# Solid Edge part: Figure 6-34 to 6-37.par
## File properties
Author: Ashutosh-CADCIM
Template: Iso Metric Part.par
Last saved by: CADCIM_Sonam
Revision: 2
Application: Solid Edge
Accuracy: 0.990
Username: Ashutosh-CADCIM
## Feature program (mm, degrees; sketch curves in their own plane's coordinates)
base feature "unnamed BaseFeature 1"
sketch for "unnamed Protrusion 1" plane through (0, 0, 0) normal (0, -1, 0) x-axis (1, 0, 0)
  line (0, 100) -> (0, 0)
  line (0, 0) -> (100, 0)
  line (100, 0) -> (100, 20)
  line (100, 20) -> (20, 20)
  line (20, 20) -> (20, 100)
  line (20, 100) -> (0, 100)
  dimension (linear) = 100
extrude "unnamed Protrusion 1" add finite 100 symmetric
sketch for "ExtrudedCutout_1" plane through (60, 0, 20) normal (0, 0, 1) x-axis (0, 1, 0)
  line (10, -20) -> (-10, -20)
  line (-10, -20) -> (-10, 20)
  line (-10, 20) -> (10, 20)
  line (10, 20) -> (10, -20)
  dimension (linear) = 10
  dimension (linear) = 10
extrude "ExtrudedCutout_1" cut finite 116.9458 symmetric
sketch for "ExtrudedCutout_2" plane through (10, 0, 100) normal (0, 0, 1) x-axis (0, 1, 0)
  line (-60.7863, 14.3845) -> (60.7863, 14.3845)
  line (60.7863, 14.3845) -> (60.7863, -14.3845)
  line (60.7863, -14.3845) -> (-60.7863, -14.3845)
  line (-60.7863, -14.3845) -> (-60.7863, 14.3845)
extrude "ExtrudedCutout_2" cut finite 31.4628 symmetric
chamfer "Chamfer_1" setback 5
chamfer "Chamfer_2" setback 5  SetBackValue2 = 45 deg
chamfer "Chamfer_3" setback 10  SetBackValue2 = 5 mm
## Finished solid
Body 1: solid body, 15 faces, 39 edges, 26 vertices.
  Faces by surface: plane 15
  Edges by curve: line 39
Bounding box of the edges (mm): 100.000 x 100.000 x 84.269, from (0, -50, 0) to (100, 50, 84.2686).
Planar faces by outward normal: +x 3, +y 2, +z 2, -x 2, -y 2, -z 1, oblique 3
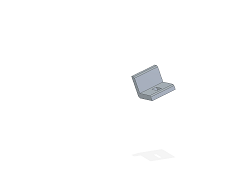
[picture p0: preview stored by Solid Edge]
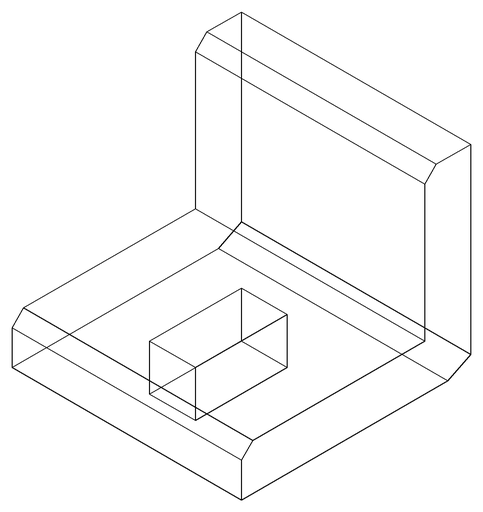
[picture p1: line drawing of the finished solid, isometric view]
